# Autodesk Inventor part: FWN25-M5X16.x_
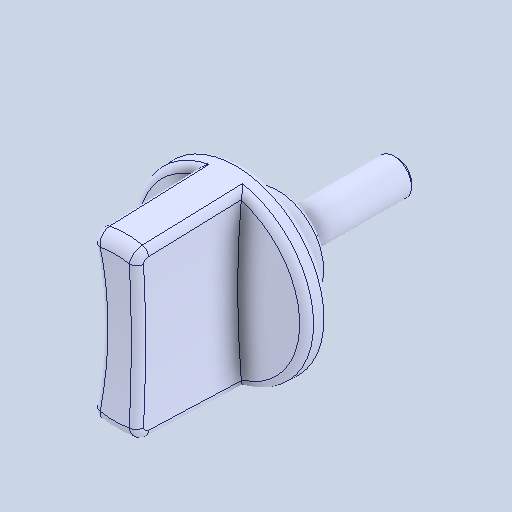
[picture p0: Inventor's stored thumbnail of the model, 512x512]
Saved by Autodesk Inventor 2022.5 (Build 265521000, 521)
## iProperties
Created: 2024-05
Part Number: FWN25-M5X16.x_
Material: 一般
Document SubType Name: Modeling
Designer: ImaoCorp
Density: 1 g/cm^3
Appearance: 既定
Author: ImaoCorp
Sending System: SOLIDWORKS 2022-2022290
MC: AMD64
MC_MODEL: Intel64 Family 6 Model 60 Stepping 3, GenuineIntel
OS: Windows_NT
FRU: Parasolid Version 33.1, build 260,  4-25-2022
FORMAT: text
GUISE: transmit
KEY: FILEFWN25-M5X16.x_t
DATE: Mon May 20 16:40:48 2024
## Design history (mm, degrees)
feature "Base1"
node "ソリッド1"
